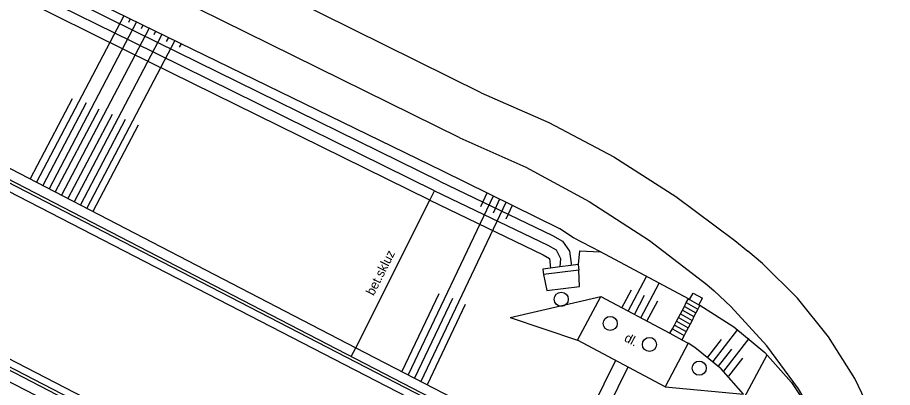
# Model space of a CAD drawing. Extents: x -539244 to -537359, y -1183785 to -1181851.
# Drawn here: x -538237.5 to -538175.6, y -1182945.4 to -1182919.2 of the extents above; entities that cross this region are included whole.
import ezdxf

# ---------------------------------------------------------------- set-up
doc = ezdxf.new("R2010")
doc.units = 0
for name, color, linetype in [('Vrstva 10', 7, 'Continuous'), ('Vrstva 11', 7, 'Continuous'), ('Vrstva 14', 7, 'Continuous'), ('Vrstva 15', 7, 'Continuous'), ('Vrstva 27', 7, 'Continuous'), ('Vrstva 40', 7, 'Continuous'), ('Vrstva 9', 7, 'Continuous')]:
    doc.layers.add(name, color=color, linetype=linetype)

msp = doc.modelspace()

# ---------------------------------------------------------------- linework, layer by layer
at = {"layer": 'Vrstva 10'}
for p, q in [((-538240.606, -1182930.158), (-538205.053, -1182948.5)), ((-538208.035, -1182958.796), (-538245.379, -1182939.535))]:
    msp.add_line(p, q, dxfattribs=at)
at = {"layer": 'Vrstva 11'}
for p, q in [((-538228.983, -1182920.226), (-538251.978, -1182908.816)), ((-538229.647, -1182921.57), (-538252.644, -1182910.16)), ((-538204.643, -1182924.511), (-538225.786, -1182914.027)), ((-538206.156, -1182927.688), (-538227.374, -1182917.212)), ((-538207.604, -1182930.764), (-538228.983, -1182920.226)), ((-538208.282, -1182932.102), (-538229.647, -1182921.57)), ((-538204.926, -1182947.996), (-538240.312, -1182929.703)), ((-538207.604, -1182930.764), (-538199.608, -1182934.601)), ((-538208.282, -1182932.102), (-538200.255, -1182935.955)), ((-538197.786, -1182936.651), (-538197.735, -1182937.048)), ((-538200.29, -1182936.971), (-538200.239, -1182937.368)), ((-538197.735, -1182937.048), (-538200.239, -1182937.368)), ((-538200.239, -1182937.368), (-538200.018, -1182938.5)), ((-538197.7, -1182938.212), (-538197.735, -1182937.048)), ((-538200.018, -1182938.5), (-538197.7, -1182938.212)), ((-538189.91, -1182939.13), (-538189.652, -1182938.668)), ((-538189.652, -1182938.668), (-538188.998, -1182939.036)), ((-538197.835, -1182942.007), (-538196.197, -1182938.913)), ((-538196.197, -1182938.913), (-538191.298, -1182941.519)), ((-538190.143, -1182939.343), (-538189.319, -1182939.804)), ((-538189.255, -1182939.496), (-538188.998, -1182939.036)), ((-538190.421, -1182939.875), (-538189.598, -1182940.335)), ((-538190.28, -1182939.611), (-538189.459, -1182940.07)), ((-538190.845, -1182940.67), (-538190.017, -1182941.132)), ((-538190.703, -1182940.404), (-538189.877, -1182940.866)), ((-538190.562, -1182940.14), (-538189.738, -1182940.601)), ((-538191.127, -1182941.199), (-538190.296, -1182941.664)), ((-538190.986, -1182940.934), (-538190.157, -1182941.398)), ((-538191.298, -1182941.519), (-538190.46, -1182941.976)), ((-538191.633, -1182945.314), (-538197.835, -1182942.007)), ((-538189.999, -1182942.214), (-538191.633, -1182945.314)), ((-538190.46, -1182941.976), (-538189.999, -1182942.214))]:
    msp.add_line(p, q, dxfattribs=at)
for points in [[(-538204.643, -1182924.511), (-538199.87, -1182926.597), (-538195.271, -1182929.043), (-538190.873, -1182931.835), (-538186.702, -1182934.955), (-538185.783, -1182935.713)], [(-538206.156, -1182927.688), (-538201.499, -1182929.758), (-538197.018, -1182932.187), (-538192.742, -1182934.959), (-538188.696, -1182938.058), (-538188.16, -1182938.508)], [(-538199.608, -1182934.601), (-538198.908, -1182934.995), (-538198.412, -1182935.711), (-538198.283, -1182936.572), (-538198.3, -1182936.717)], [(-538175.556, -1182951.171), (-538176.7, -1182947.869), (-538178.213, -1182944.72), (-538180.077, -1182941.763), (-538182.265, -1182939.039), (-538184.75, -1182936.583), (-538185.783, -1182935.713)], [(-538200.255, -1182935.955), (-538199.829, -1182936.216), (-538199.757, -1182936.903)], [(-538197.786, -1182936.651), (-538198.3, -1182936.717), (-538199.098, -1182936.819), (-538199.757, -1182936.903), (-538200.29, -1182936.971)], [(-538178.738, -1182952.154), (-538180.29, -1182948.708), (-538182.197, -1182945.444), (-538184.438, -1182942.401), (-538186.988, -1182939.611), (-538188.16, -1182938.508)], [(-538191.298, -1182941.519), (-538191.127, -1182941.199), (-538190.986, -1182940.934), (-538190.845, -1182940.67), (-538190.703, -1182940.404), (-538190.562, -1182940.14), (-538190.421, -1182939.875), (-538190.28, -1182939.611), (-538190.143, -1182939.343), (-538189.997, -1182939.081)], [(-538189.997, -1182939.081), (-538189.91, -1182939.13), (-538189.255, -1182939.496), (-538189.18, -1182939.538)], [(-538208.271, -1182959.282), (-538218.978, -1182953.745), (-538245.6, -1182939.981)], [(-538189.18, -1182939.538), (-538189.319, -1182939.804), (-538189.459, -1182940.07), (-538189.598, -1182940.335), (-538189.738, -1182940.601), (-538189.877, -1182940.866), (-538190.017, -1182941.132), (-538190.157, -1182941.398), (-538190.296, -1182941.664), (-538190.46, -1182941.976)]]:
    msp.add_lwpolyline(points, dxfattribs=at)
at = {"layer": 'Vrstva 14'}
for p, q in [((-538228.623, -1182919.692), (-538251.778, -1182908.363)), ((-538229.315, -1182920.898), (-538252.311, -1182909.488)), ((-538207.369, -1182930.052), (-538228.623, -1182919.692)), ((-538207.945, -1182931.432), (-538229.315, -1182920.898)), ((-538199.088, -1182934.138), (-538207.369, -1182930.052)), ((-538207.945, -1182931.432), (-538199.93, -1182935.279)), ((-538198.129, -1182934.754), (-538199.088, -1182934.138)), ((-538196.221, -1182935.748), (-538198.129, -1182934.754)), ((-538197.694, -1182935.685), (-538197.786, -1182936.651)), ((-538197.694, -1182935.685), (-538196.221, -1182935.748)), ((-538189.997, -1182939.081), (-538196.221, -1182935.748)), ((-538202.607, -1182940.392), (-538196.197, -1182938.913)), ((-538202.607, -1182940.392), (-538197.835, -1182942.007)), ((-538213.842, -1182943.161), (-538213.528, -1182942.535)), ((-538191.633, -1182945.314), (-538186.088, -1182945.825))]:
    msp.add_line(p, q, dxfattribs=at)
for points in [[(-538239.865, -1182928.882), (-538213.528, -1182942.535), (-538204.537, -1182947.195)], [(-538213.528, -1182942.535), (-538208.282, -1182932.102), (-538207.945, -1182931.432)], [(-538199.93, -1182935.279), (-538199.344, -1182935.618), (-538199.043, -1182936.224), (-538199.098, -1182936.819)], [(-538189.18, -1182939.538), (-538186.768, -1182941.051), (-538184.591, -1182942.886), (-538182.692, -1182945.008), (-538181.11, -1182947.375), (-538179.874, -1182949.941), (-538179.009, -1182952.654), (-538178.532, -1182955.461), (-538178.454, -1182958.307), (-538178.531, -1182959.414)], [(-538246.078, -1182940.794), (-538219.398, -1182954.553), (-538210.451, -1182959.167)], [(-538186.088, -1182945.825), (-538187.67, -1182944.029), (-538189.528, -1182942.521), (-538189.999, -1182942.214)]]:
    msp.add_lwpolyline(points, dxfattribs=at)
at = {"layer": 'Vrstva 15'}
for p, q in [((-538229.928, -1182919.054), (-538236.109, -1182930.829)), ((-538229.028, -1182919.494), (-538235.22, -1182931.29)), ((-538229.478, -1182919.274), (-538229.609, -1182919.524)), ((-538228.13, -1182919.932), (-538234.333, -1182931.75)), ((-538228.579, -1182919.713), (-538228.714, -1182919.97)), ((-538227.68, -1182920.152), (-538227.809, -1182920.397)), ((-538227.231, -1182920.371), (-538233.445, -1182932.21)), ((-538226.331, -1182920.809), (-538232.557, -1182932.67)), ((-538226.781, -1182920.59), (-538226.925, -1182920.865)), ((-538225.881, -1182921.028), (-538226.015, -1182921.283)), ((-538233.572, -1182924.92), (-538236.553, -1182930.599)), ((-538232.599, -1182925.22), (-538235.664, -1182931.06)), ((-538231.697, -1182925.653), (-538234.776, -1182931.52)), ((-538230.765, -1182926.029), (-538233.889, -1182931.98)), ((-538229.829, -1182926.397), (-538233.001, -1182932.44)), ((-538228.908, -1182926.794), (-538232.113, -1182932.9)), ((-538203.797, -1182931.815), (-538209.81, -1182944.462)), ((-538204.245, -1182931.594), (-538204.706, -1182932.564)), ((-538202.899, -1182932.258), (-538208.921, -1182944.923)), ((-538203.348, -1182932.036), (-538203.81, -1182933.008)), ((-538202.451, -1182932.478), (-538202.905, -1182933.432)), ((-538194.25, -1182939.948), (-538192.953, -1182937.498)), ((-538193.367, -1182940.418), (-538192.071, -1182937.97)), ((-538207.636, -1182938.728), (-538210.253, -1182944.232)), ((-538194.692, -1182939.714), (-538194.021, -1182938.446)), ((-538193.809, -1182940.183), (-538193.088, -1182938.822)), ((-538206.684, -1182939.052), (-538209.365, -1182944.692)), ((-538192.926, -1182940.653), (-538192.167, -1182939.22)), ((-538205.785, -1182939.492), (-538208.477, -1182945.153)), ((-538188.232, -1182943.517), (-538186.487, -1182941.259)), ((-538187.495, -1182944.2), (-538185.704, -1182941.882)), ((-538188.616, -1182943.198), (-538187.663, -1182941.965)), ((-538190.036, -1182953.49), (-538184.425, -1182943.049)), ((-538187.858, -1182943.852), (-538186.913, -1182942.629)), ((-538195.155, -1182943.436), (-538198.278, -1182949.783)), ((-538187.143, -1182944.562), (-538186.151, -1182943.277)), ((-538194.272, -1182943.907), (-538197.351, -1182950.167))]:
    msp.add_line(p, q, dxfattribs=at)
at = {"layer": 'Vrstva 27'}
for centre in [(-538198.987, -1182939.111), (-538195.525, -1182940.819), (-538192.746, -1182942.309), (-538189.226, -1182943.984)]:
    msp.add_circle(centre, 0.5, dxfattribs=at)
at = {"layer": 'Vrstva 9'}
for p, q in [((-538204.768, -1182947.852), (-538240.22, -1182929.525)), ((-538245.692, -1182940.159), (-538210.145, -1182958.538))]:
    msp.add_line(p, q, dxfattribs=at)

# ---------------------------------------------------------------- texts
at = {"layer": 'Vrstva 40'}
for s, rotation, p in [('bet.skluz', 63.30864, (-538212.26, -1182938.902)), ('dl.', 331.93279, (-538194.587, -1182942.039))]:
    msp.add_text(s, height=0.65, rotation=rotation, dxfattribs=at).set_placement(p)

doc.saveas('drawing.dxf')
